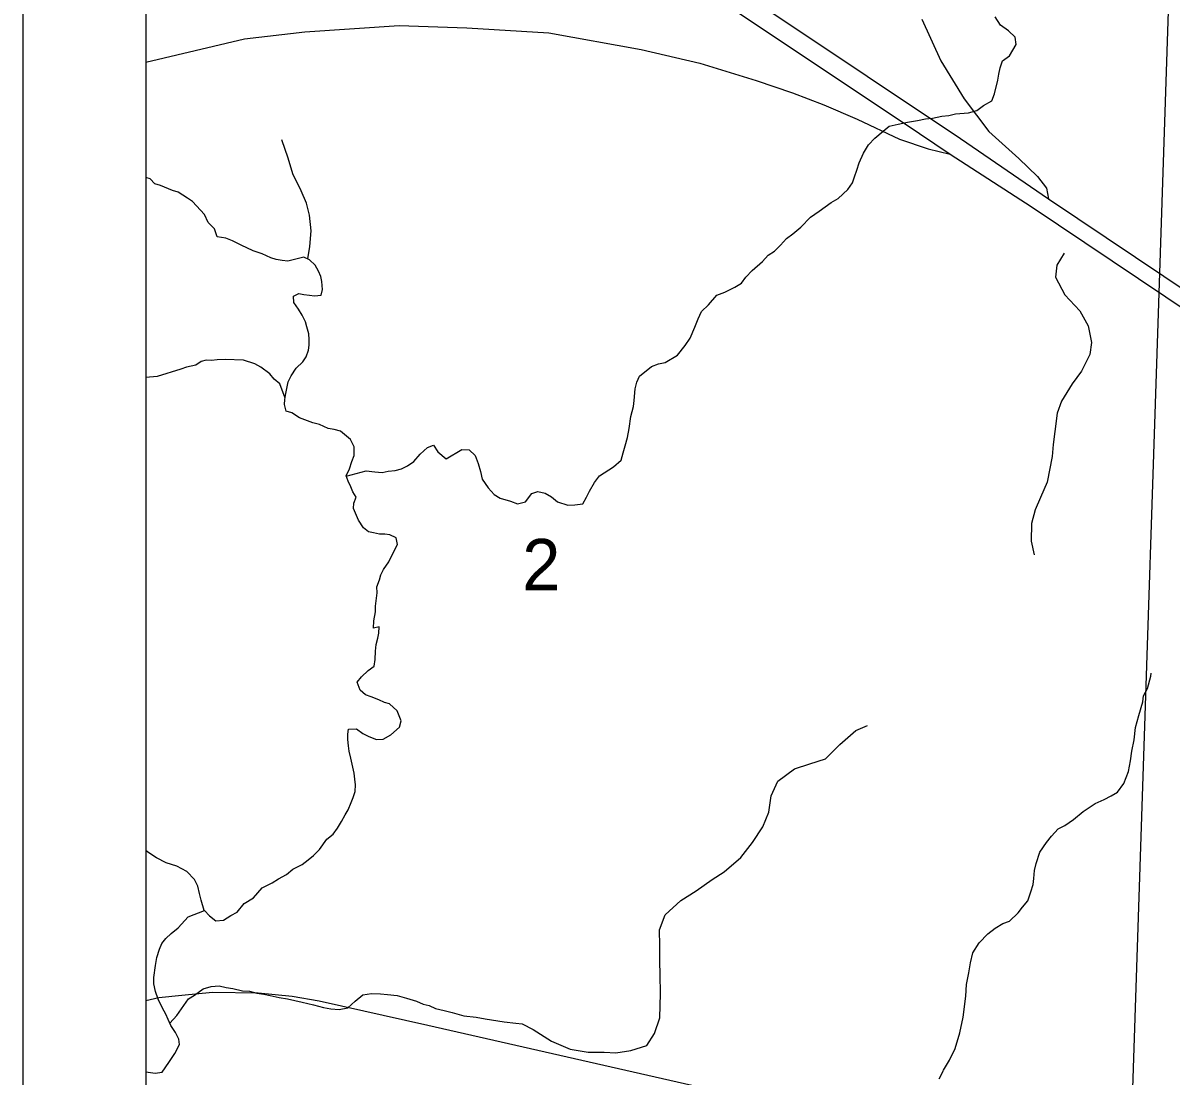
# Model space of a CAD drawing. Extents: x 0 to 34, y 0 to 22.
# Drawn here: x 2 to 2.934, y 16.896 to 17.753 of the extents above; entities that cross this region are included whole.
import ezdxf

# ---------------------------------------------------------------- set-up
doc = ezdxf.new("R2010")
doc.units = 0
for name, color, linetype in [('Default', 7, 'Continuous'), ('GM_X_Interstate_Route', 7, 'Continuous'), ('GM_X_Minor_River', 7, 'Continuous'), ('GM_X_Section', 7, 'Continuous'), ('GM_X_Section_Text', 7, 'Continuous'), ('GM_X_State_Route', 7, 'Continuous'), ('GM_X_US_Route', 7, 'Continuous'), ('SH_Data', 7, 'Continuous')]:
    doc.layers.add(name, color=color, linetype=linetype)

msp = doc.modelspace()

# ---------------------------------------------------------------- linework, layer by layer
at = {"layer": 'Default'}
msp.add_lwpolyline([(2.1, 17.82435), (2.1, 16.83006), (2.90066, 16.8204), (2.93343, 17.81142)], close=True, dxfattribs=at)
at = {"layer": 'GM_X_Interstate_Route'}
msp.add_line((2.72934, 17.66252), (2.75429, 17.64585), dxfattribs=at)
for points in [[(2.1, 18.11832), (2.1593, 18.07387), (2.34688, 17.93806), (2.3612, 17.92827), (2.53392, 17.81133), (2.76268, 17.65846), (2.8343, 17.60933), (3.4225, 17.21495)], [(2.1, 18.09942), (2.15092, 18.06126), (2.33243, 17.9297), (2.34616, 17.91974), (2.52553, 17.79872), (2.72934, 17.66252)], [(2.73107, 17.75559), (2.7465, 17.72175), (2.76549, 17.69087), (2.78568, 17.66415), (2.81002, 17.64218), (2.82518, 17.62768), (2.83244, 17.61819), (2.8343, 17.60933)], [(2.1, 17.72065), (2.18028, 17.7395), (2.22935, 17.74522), (2.30596, 17.75034), (2.36103, 17.74858), (2.42782, 17.74448), (2.50294, 17.73095), (2.55054, 17.71976), (2.59638, 17.70572), (2.62598, 17.69564), (2.65143, 17.68577), (2.67862, 17.67414), (2.71306, 17.65791), (2.73631, 17.65001), (2.75429, 17.64585)], [(2.75429, 17.64585), (2.82009, 17.6033), (3.08288, 17.42696)]]:
    msp.add_lwpolyline(points, dxfattribs=at)
at = {"layer": 'GM_X_Minor_River'}
for points in [[(2.35696, 17.40551), (2.36303, 17.4053), (2.36781, 17.40057), (2.37024, 17.39403), (2.37229, 17.3875), (2.3736, 17.38137), (2.37829, 17.37437), (2.38342, 17.36887), (2.38825, 17.36604), (2.39652, 17.36348), (2.40214, 17.36138), (2.40865, 17.36305), (2.41382, 17.36971), (2.41881, 17.37144), (2.42484, 17.37009), (2.43004, 17.36687), (2.43484, 17.36291), (2.44311, 17.36034), (2.44881, 17.36053), (2.45529, 17.36144), (2.45851, 17.36665), (2.46096, 17.3715), (2.465, 17.37859), (2.46899, 17.38415), (2.48025, 17.39136), (2.48651, 17.39684), (2.48824, 17.40286), (2.48995, 17.4085), (2.4917, 17.41528), (2.49309, 17.42246), (2.49457, 17.43228), (2.49675, 17.44057), (2.4973, 17.44549), (2.49801, 17.45497), (2.49933, 17.46024), (2.5014, 17.46511), (2.51117, 17.47313), (2.51693, 17.47521), (2.52228, 17.47617), (2.53236, 17.48228), (2.53871, 17.49004), (2.54271, 17.49598), (2.54644, 17.50498), (2.54933, 17.51172), (2.55181, 17.51771), (2.5577, 17.52321), (2.56442, 17.53096), (2.57096, 17.53339), (2.57908, 17.53767), (2.5845, 17.5409), (2.58809, 17.54572), (2.59322, 17.55124), (2.60144, 17.55856), (2.60617, 17.56371), (2.61122, 17.56696), (2.61632, 17.57172), (2.62107, 17.57726), (2.62613, 17.58088), (2.63278, 17.58635), (2.64065, 17.59444), (2.64766, 17.59952), (2.65738, 17.6064), (2.66319, 17.60962), (2.67104, 17.61695), (2.67465, 17.62253), (2.67634, 17.62741), (2.67842, 17.63266), (2.68014, 17.63868), (2.68383, 17.64653), (2.68786, 17.65323), (2.69299, 17.65876), (2.69964, 17.66461), (2.70472, 17.66861), (2.71199, 17.67026), (2.71963, 17.67189), (2.72765, 17.67314), (2.73415, 17.67443), (2.73987, 17.67499), (2.74752, 17.67663), (2.75323, 17.67719), (2.75859, 17.67853), (2.76925, 17.6793), (2.77577, 17.68135), (2.78123, 17.68534), (2.7882, 17.68928), (2.79029, 17.69491), (2.79295, 17.70584), (2.79387, 17.71075), (2.79482, 17.71604), (2.79691, 17.72167), (2.80236, 17.72566), (2.808, 17.73496), (2.80707, 17.74107), (2.80156, 17.74621), (2.79525, 17.7506), (2.79094, 17.7576)], [(2.23169, 17.56056), (2.23337, 17.57053), (2.23451, 17.58342), (2.23297, 17.59601), (2.2306, 17.60596), (2.22633, 17.61596), (2.21952, 17.62984), (2.2157, 17.6425), (2.21044, 17.65747)], [(2.15073, 17.59013), (2.14754, 17.5967), (2.13804, 17.60729), (2.13396, 17.61009), (2.12615, 17.61492), (2.12164, 17.61622), (2.11191, 17.62036), (2.1074, 17.62165), (2.10336, 17.62559), (2.1, 17.62685)], [(2.30444, 17.19299), (2.29818, 17.19853), (2.29405, 17.19981), (2.28956, 17.20187), (2.2832, 17.20437), (2.2787, 17.20605), (2.27427, 17.20962), (2.27183, 17.21616), (2.2754, 17.2206), (2.2809, 17.22573), (2.28558, 17.22937), (2.28652, 17.23466), (2.28675, 17.24149), (2.28732, 17.24679), (2.28864, 17.25206), (2.28954, 17.25621), (2.28971, 17.26115), (2.28512, 17.26017), (2.28533, 17.26624), (2.28672, 17.27341), (2.28688, 17.27796), (2.28802, 17.28895), (2.28781, 17.29389), (2.2899, 17.29952), (2.29118, 17.30366), (2.29322, 17.30777), (2.29761, 17.31407), (2.30252, 17.32417), (2.30456, 17.32828), (2.30361, 17.33363), (2.29838, 17.33609), (2.29422, 17.33662), (2.29005, 17.33676), (2.28514, 17.33769), (2.281, 17.33859), (2.27693, 17.34177), (2.27297, 17.34799), (2.26875, 17.35764), (2.26927, 17.3618), (2.27096, 17.36668), (2.26845, 17.37095), (2.2667, 17.37519), (2.26458, 17.37982), (2.26283, 17.38407), (2.26568, 17.38967), (2.2674, 17.39569), (2.26947, 17.40056), (2.26934, 17.40778), (2.2665, 17.41358), (2.25838, 17.42032), (2.25311, 17.42165), (2.24821, 17.42258), (2.24111, 17.42586), (2.23584, 17.42718), (2.23135, 17.42886), (2.22498, 17.43136), (2.21866, 17.43538), (2.21415, 17.43668), (2.21281, 17.44204), (2.21296, 17.44622), (2.21389, 17.45113), (2.21573, 17.46056), (2.21818, 17.46542), (2.22219, 17.47174), (2.22769, 17.47687), (2.23049, 17.48096), (2.23219, 17.48622), (2.23271, 17.49038), (2.23287, 17.49493), (2.23264, 17.4995), (2.23095, 17.50526), (2.22995, 17.50948), (2.2271, 17.5149), (2.22423, 17.51956), (2.22024, 17.52501), (2.22004, 17.53034), (2.22429, 17.53248), (2.22844, 17.53157), (2.23298, 17.53103), (2.23713, 17.53051), (2.24247, 17.53108), (2.24377, 17.5356), (2.24323, 17.54208), (2.24224, 17.5463), (2.24048, 17.55054), (2.23762, 17.55557), (2.23321, 17.55991), (2.22835, 17.56198), (2.22299, 17.56064), (2.21533, 17.55863), (2.21079, 17.55917), (2.20588, 17.5601), (2.20175, 17.56138), (2.19465, 17.56466), (2.18715, 17.56721), (2.17743, 17.57172), (2.17035, 17.57539), (2.1651, 17.57747), (2.15792, 17.57848), (2.15587, 17.58501), (2.15073, 17.59013)], [(2.84698, 17.56516), (2.841, 17.55544), (2.83996, 17.54559), (2.84752, 17.53131), (2.85968, 17.51842), (2.86654, 17.50606), (2.86919, 17.49268), (2.86777, 17.48284), (2.86092, 17.46935), (2.8534, 17.45892), (2.84464, 17.44472), (2.84132, 17.43493), (2.83937, 17.42017), (2.83792, 17.40956), (2.83726, 17.3997), (2.83324, 17.37891), (2.82756, 17.36653), (2.82347, 17.35638), (2.8205, 17.34544), (2.82008, 17.33101), (2.82242, 17.31992)], [(2.21316, 17.44726), (2.20884, 17.4589), (2.20442, 17.46286), (2.20078, 17.46716), (2.19336, 17.47236), (2.18853, 17.47519), (2.17952, 17.47816), (2.16435, 17.47869), (2.15789, 17.47853), (2.15331, 17.47793), (2.14914, 17.47807), (2.14493, 17.47708), (2.14065, 17.47419), (2.133, 17.47255), (2.12839, 17.47081), (2.1092, 17.46501), (2.1, 17.46407)], [(2.26292, 17.38385), (2.27929, 17.38806), (2.2861, 17.38744), (2.29216, 17.38685), (2.29713, 17.38782), (2.30284, 17.38838), (2.30782, 17.38973), (2.31285, 17.39221), (2.31791, 17.39584), (2.32304, 17.40174), (2.32893, 17.40724), (2.33392, 17.40897), (2.33753, 17.40352), (2.34418, 17.39797), (2.35696, 17.40551)], [(2.74832, 16.89965), (2.74515, 16.8935), (2.74881, 16.90059), (2.75365, 16.90879), (2.75815, 16.91813), (2.76201, 16.93092), (2.76473, 16.94374), (2.76683, 16.96077), (2.76754, 16.97024), (2.76938, 16.97968), (2.77081, 16.98799), (2.7726, 16.99591), (2.77782, 17.00409), (2.78491, 17.01144), (2.79077, 17.01618), (2.79696, 17.01976), (2.80235, 17.02186), (2.80941, 17.02845), (2.813, 17.03327), (2.81735, 17.03844), (2.81988, 17.04557), (2.8216, 17.05159), (2.82215, 17.05651), (2.82275, 17.06295), (2.82409, 17.0686), (2.82707, 17.078), (2.83265, 17.08579), (2.83663, 17.09097), (2.84215, 17.09686), (2.84756, 17.09971), (2.85456, 17.10441), (2.86238, 17.11098), (2.87209, 17.11748), (2.87942, 17.12065), (2.88522, 17.12387), (2.89026, 17.12674), (2.89544, 17.13378), (2.89919, 17.14353), (2.90101, 17.1522), (2.90204, 17.16015), (2.90387, 17.16921), (2.90499, 17.17943), (2.9076, 17.18922), (2.91101, 17.20012), (2.91156, 17.20504), (2.91481, 17.21101), (2.91743, 17.22118), (2.91783, 17.2235)], [(2.1, 16.89925), (2.10747, 16.89809), (2.1132, 16.89903), (2.11878, 16.90682), (2.1236, 16.91425), (2.12726, 16.92135), (2.12666, 16.92593), (2.12419, 16.93133), (2.1202, 16.93679), (2.11809, 16.9418), (2.11634, 16.94604), (2.11348, 16.95108), (2.10993, 16.95842), (2.10787, 16.96458), (2.10656, 16.9707), (2.10636, 16.97603), (2.10784, 16.98586), (2.10882, 16.99228), (2.11095, 16.99905), (2.11301, 17.00354), (2.11619, 17.00761), (2.1205, 17.01164), (2.12636, 17.01638), (2.13426, 17.02522), (2.14773, 17.03046), (2.15175, 17.02614), (2.15693, 17.02216), (2.16303, 17.02271), (2.16922, 17.02629), (2.17426, 17.02916), (2.17982, 17.03618), (2.18757, 17.04086), (2.19468, 17.04897), (2.20279, 17.05287), (2.20784, 17.05611), (2.21442, 17.05969), (2.2195, 17.06407), (2.22723, 17.06798), (2.23191, 17.07162), (2.23622, 17.07527), (2.24132, 17.08004), (2.24731, 17.08857), (2.25238, 17.09257), (2.25596, 17.09739), (2.25919, 17.10298), (2.26203, 17.1082), (2.26445, 17.1123), (2.26694, 17.11829), (2.2686, 17.12241), (2.27028, 17.12729), (2.27047, 17.13261), (2.26987, 17.13719), (2.26928, 17.14215), (2.26667, 17.1544), (2.26534, 17.16015), (2.26473, 17.16435), (2.26415, 17.16969), (2.2643, 17.17386), (2.26482, 17.17803), (2.27128, 17.17818), (2.27647, 17.17458), (2.28132, 17.17213), (2.28769, 17.16963), (2.29301, 17.16983), (2.29921, 17.17341), (2.30626, 17.17963), (2.30758, 17.1849), (2.30444, 17.19299)], [(2.40593, 16.9382), (2.41512, 16.93359), (2.43004, 16.92404), (2.44505, 16.91753), (2.45979, 16.91521), (2.4727, 16.91522), (2.48218, 16.91457), (2.49439, 16.9165), (2.50742, 16.92069), (2.51378, 16.93039), (2.51795, 16.94319), (2.51852, 16.96294), (2.5182, 16.97815), (2.51814, 16.98918), (2.51812, 17.00172), (2.51773, 17.01466), (2.52227, 17.02707), (2.53513, 17.03849), (2.54752, 17.04649), (2.56069, 17.05562), (2.57037, 17.06181), (2.584, 17.07358), (2.59347, 17.08585), (2.60181, 17.09854), (2.60672, 17.11056), (2.60862, 17.12381), (2.6139, 17.13582), (2.62748, 17.1457), (2.64014, 17.1499), (2.65278, 17.15372), (2.66452, 17.16554), (2.67738, 17.17696), (2.68699, 17.18087)], [(2.14751, 17.03038), (2.14498, 17.03891), (2.14365, 17.04428), (2.14234, 17.0504), (2.13949, 17.05582), (2.13325, 17.06212), (2.12506, 17.06658), (2.11641, 17.06916), (2.10858, 17.07323), (2.10153, 17.07804), (2.1, 17.0792)], [(2.11935, 16.9388), (2.12504, 16.94498), (2.12903, 16.95054), (2.13462, 16.95871), (2.13966, 16.96158), (2.14667, 16.96665), (2.15319, 16.96871), (2.15966, 16.96924), (2.16531, 16.96791), (2.1706, 16.96696), (2.1785, 16.96517), (2.18419, 16.96497), (2.19021, 16.96325), (2.19587, 16.96229), (2.20115, 16.96135), (2.20831, 16.95958), (2.2151, 16.95858), (2.22716, 16.95589), (2.2362, 16.95367), (2.24447, 16.95149), (2.25052, 16.95052), (2.25733, 16.9499), (2.26421, 16.95118), (2.27009, 16.95668), (2.27634, 16.96178), (2.2836, 16.96305), (2.2908, 16.9628), (2.29648, 16.96223), (2.30442, 16.96119), (2.31194, 16.95903), (2.32021, 16.95684), (2.32544, 16.95438), (2.33033, 16.95307), (2.33556, 16.95061), (2.34273, 16.94923), (2.34912, 16.94748), (2.35853, 16.94488), (2.36874, 16.94377), (2.3759, 16.94238), (2.39138, 16.93994), (2.40084, 16.93885), (2.40593, 16.9382)]]:
    msp.add_lwpolyline(points, dxfattribs=at)
at = {"layer": 'GM_X_Section'}
msp.add_lwpolyline([(3.92299, 17.79649), (3.90541, 16.80662), (2.90066, 16.8204), (2.93343, 17.81142)], close=True, dxfattribs=at)
at = {"layer": 'GM_X_State_Route'}
for points in [[(2.1, 19.81084), (2.1, 16.74079)], [(2.1, 16.95733), (2.1106, 16.95966), (2.12916, 16.9615), (2.15424, 16.96415), (2.19134, 16.96353), (2.21887, 16.96068), (2.24089, 16.95701), (2.32937, 16.93723), (2.59178, 16.87749), (2.6768, 16.85833), (2.71024, 16.84895), (2.75387, 16.83407), (2.96591, 16.7415), (3.04828, 16.70562), (3.10945, 16.68237), (3.16959, 16.66199), (3.23728, 16.64608), (3.29988, 16.63711), (3.3641, 16.63181), (3.42486, 16.63099)]]:
    msp.add_lwpolyline(points, dxfattribs=at)
at = {"layer": 'GM_X_US_Route'}
msp.add_line((2.72934, 17.66252), (2.75429, 17.64585), dxfattribs=at)
for points in [[(2.1, 18.09942), (2.15092, 18.06126), (2.33243, 17.9297), (2.34616, 17.91974), (2.52553, 17.79872), (2.72934, 17.66252)], [(2.75429, 17.64585), (2.82009, 17.6033), (3.08288, 17.42696)]]:
    msp.add_lwpolyline(points, dxfattribs=at)
at = {"layer": 'SH_Data'}
for p, q in [((2, 21), (2, 14)), ((2.1, 20.9), (2.1, 14.1))]:
    msp.add_line(p, q, dxfattribs=at)

# ---------------------------------------------------------------- texts
at = {"layer": 'GM_X_Section_Text'}
msp.add_text('2', height=0.04186, rotation=0.00001, dxfattribs=at).set_placement((2.40606, 17.29089))

doc.saveas('drawing.dxf')
